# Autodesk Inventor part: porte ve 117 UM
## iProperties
Shininess: 20.0
Length Units: 11269
Angle Units: 11279
Time Units: 11290
Mass Units: 11283
Length Display Precision: 3
Angle Display Precision: 2
Created: 2001-02
Part Number: porte ve 117 UM
Material: Par défaut
Document SubType Name: Tôlerie
Designer: Administrateur
Density: 0.0
Volumn: 0.0
Area: 0.0
PropertySet Name: Model Information
Control State: 0
Master: False
Checked Out: False
Author: Administrateur
